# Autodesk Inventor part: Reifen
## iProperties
Author: 42964
Shininess: 62.0
PropertySet Name: _Private Model Information
Length Units: 11269
Angle Units: 11283
Time Units: 11279
Mass Units: 11290
Length Display Precision: 3
Angle Display Precision: 2
Compacted: False
Created: 2000-11
Part Number: Reifen
Document SubType Name: Modeling
Designer: 42964
Control State: 0
Master: False
Checked Out: False
PropertySet Name: Design Tracking Control
Density: 0.0
Volumn: 0.0
Area: 0.0
PropertySet Name: Model Information
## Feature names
1. Revolution1
2. Extrusion1
3. Revolution2
